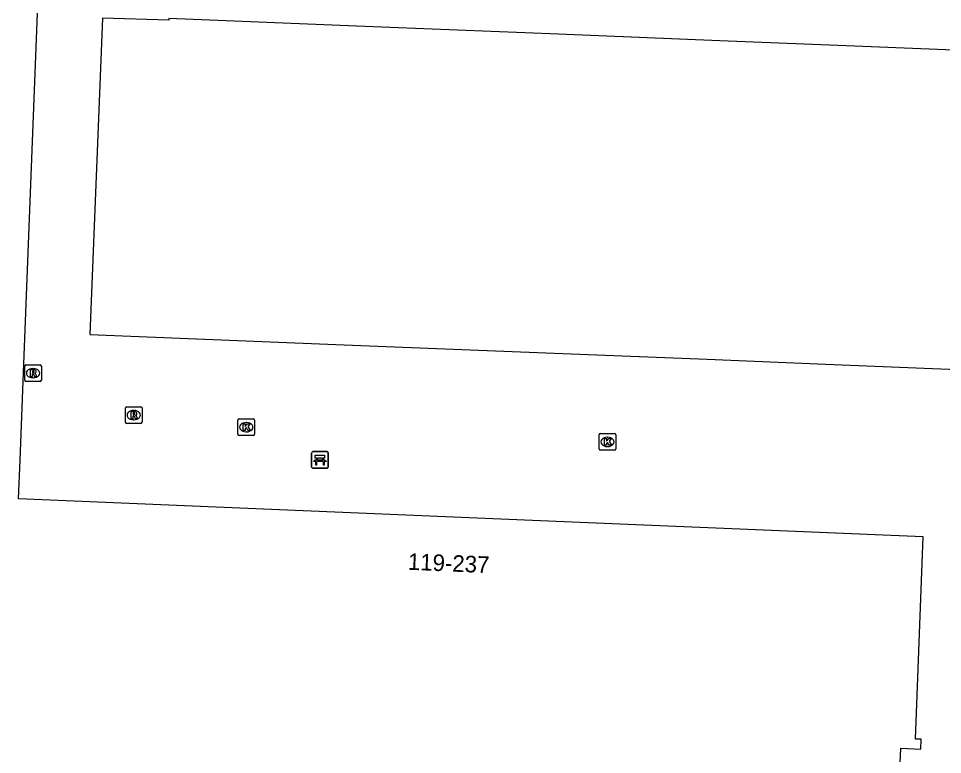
# Model space of a CAD drawing. Extents: x 160891 to 161384, y 386490 to 386907.
# Drawn here: x 161041.8 to 161097.4, y 386537.2 to 386581.5 of the extents above; entities that cross this region are included whole.
import ezdxf

# ---------------------------------------------------------------- set-up
doc = ezdxf.new("R2010")
doc.units = 0
for name, color, linetype in [('IMGEO_Bank', 7, 'Continuous'), ('IMGEO_Kolk', 7, 'Continuous'), ('IMGEO_Pand', 7, 'Continuous'), ('IMGEO_Pand_nummerreeks', 7, 'Continuous'), ('IMGEO_Rioolput', 7, 'Continuous')]:
    doc.layers.add(name, color=color, linetype=linetype)

msp = doc.modelspace()

# ---------------------------------------------------------------- linework, layer by layer
at = {"layer": 'IMGEO_Bank'}
for p, q in [((161059.471, 386554.487), (161059.471, 386555.328)), ((161059.471, 386555.328), (161059.471, 386554.487)), ((161059.546, 386555.412), (161060.387, 386555.412)), ((161060.387, 386555.412), (161059.546, 386555.412)), ((161060.471, 386555.337), (161060.471, 386554.496)), ((161060.471, 386554.496), (161060.471, 386555.337)), ((161060.168, 386554.81), (161059.775, 386554.81)), ((161059.78, 386554.918), (161059.78, 386555.024)), ((161059.824, 386555.024), (161059.824, 386554.918)), ((161060.112, 386555.03), (161059.83, 386555.03)), ((161059.83, 386554.912), (161060.112, 386554.912)), ((161060.118, 386554.918), (161060.118, 386555.024)), ((161060.162, 386555.024), (161060.162, 386554.918)), ((161060.396, 386554.412), (161059.555, 386554.412)), ((161059.555, 386554.412), (161060.396, 386554.412))]:
    msp.add_line(p, q, dxfattribs=at)
for points in [[(161059.774, 386555.03), (161059.688, 386555.03), (161059.688, 386555.191), (161060.251, 386555.191), (161060.251, 386555.03), (161060.168, 386555.03)], [(161059.718, 386554.81), (161059.576, 386554.81), (161059.688, 386554.912), (161059.774, 386554.912)], [(161059.768, 386554.803), (161059.768, 386554.596), (161059.725, 386554.596), (161059.725, 386554.803)], [(161060.168, 386554.912), (161060.251, 386554.912), (161060.363, 386554.81), (161060.224, 386554.81)], [(161060.218, 386554.803), (161060.218, 386554.596), (161060.174, 386554.596), (161060.174, 386554.803)]]:
    msp.add_lwpolyline(points, dxfattribs=at)
for centre, radius, start, end in [((161059.549, 386555.334), 0.0779, 92.4484, 184.2845), ((161059.549, 386555.334), 0.0779, 92.4484, 184.2845), ((161060.393, 386555.334), 0.0779, 2.4484, 94.2845), ((161060.393, 386555.334), 0.0779, 2.4484, 94.2845), ((161059.718, 386554.803), 0.00671, 2.8957, 87.1043), ((161059.775, 386554.803), 0.00671, 92.8957, 177.1043), ((161059.773, 386555.023), 0.00671, 2.8957, 87.1043), ((161059.773, 386554.919), 0.00671, 272.8957, 357.1043), ((161059.83, 386555.023), 0.00671, 92.8957, 177.1043), ((161059.83, 386554.919), 0.00671, 182.8957, 267.1043), ((161060.112, 386555.023), 0.00671, 2.8957, 87.1043), ((161060.112, 386554.919), 0.00671, 272.8957, 357.1043), ((161060.169, 386555.023), 0.00671, 92.8957, 177.1043), ((161060.169, 386554.919), 0.00671, 182.8957, 267.1043), ((161060.167, 386554.803), 0.00671, 2.8957, 87.1043), ((161060.224, 386554.803), 0.00671, 92.8957, 177.1043), ((161059.549, 386554.49), 0.0779, 182.4484, 274.2845), ((161059.549, 386554.49), 0.0779, 182.4484, 274.2845), ((161060.393, 386554.49), 0.0779, 272.4484, 4.2845), ((161060.393, 386554.49), 0.0779, 272.4484, 4.2845)]:
    msp.add_arc(centre, radius, start, end, dxfattribs=at)
at = {"layer": 'IMGEO_Kolk'}
for p, q in [((161055.035, 386556.459), (161055.035, 386557.311)), ((161055.11, 386557.385), (161055.962, 386557.385)), ((161055.523, 386557.165), (161055.548, 386557.165)), ((161056.036, 386557.311), (161056.036, 386556.459)), ((161055.962, 386556.385), (161055.11, 386556.385)), ((161055.546, 386556.605), (161055.521, 386556.605)), ((161076.769, 386555.574), (161076.769, 386556.426)), ((161076.844, 386556.5), (161077.696, 386556.5)), ((161077.77, 386556.426), (161077.77, 386555.574)), ((161077.257, 386556.28), (161077.282, 386556.28)), ((161077.696, 386555.5), (161076.844, 386555.5)), ((161077.28, 386555.72), (161077.255, 386555.72))]:
    msp.add_line(p, q, dxfattribs=at)
for points in [[(161055.035, 386556.459), (161055.035, 386557.311)], [(161055.11, 386557.385), (161055.962, 386557.385)], [(161055.356, 386557.085), (161055.479, 386557.085), (161055.479, 386556.934), (161055.609, 386557.085), (161055.773, 386557.085), (161055.627, 386556.934), (161055.78, 386556.685), (161055.628, 386556.685), (161055.543, 386556.849), (161055.479, 386556.782), (161055.479, 386556.685), (161055.356, 386556.685), (161055.356, 386557.085)], [(161056.036, 386557.311), (161056.036, 386556.459)], [(161055.962, 386556.385), (161055.11, 386556.385)], [(161076.769, 386555.574), (161076.769, 386556.426)], [(161076.844, 386556.5), (161077.696, 386556.5)], [(161077.77, 386556.426), (161077.77, 386555.574)], [(161077.09, 386556.2), (161077.213, 386556.2), (161077.213, 386556.049), (161077.343, 386556.2), (161077.507, 386556.2), (161077.361, 386556.049), (161077.514, 386555.8), (161077.362, 386555.8), (161077.277, 386555.964), (161077.213, 386555.897), (161077.213, 386555.8), (161077.09, 386555.8), (161077.09, 386556.2)], [(161077.696, 386555.5), (161076.844, 386555.5)]]:
    msp.add_lwpolyline(points, dxfattribs=at)
for centre, start, end in [((161055.112, 386557.309), 91.552, 178.448), ((161055.112, 386557.309), 91.552, 178.448), ((161055.96, 386557.309), 1.552, 88.448), ((161055.96, 386557.309), 1.552, 88.448), ((161055.112, 386556.461), 181.552, 268.448), ((161055.112, 386556.461), 181.552, 268.448), ((161055.96, 386556.461), 271.552, 358.448), ((161055.96, 386556.461), 271.552, 358.448), ((161076.846, 386556.424), 91.552, 178.448), ((161076.846, 386556.424), 91.552, 178.448), ((161077.694, 386556.424), 1.552, 88.448), ((161077.694, 386556.424), 1.552, 88.448), ((161076.846, 386555.576), 181.552, 268.448), ((161076.846, 386555.576), 181.552, 268.448), ((161077.694, 386555.576), 271.552, 358.448), ((161077.694, 386555.576), 271.552, 358.448)]:
    msp.add_arc(centre, 0.0765, start, end, dxfattribs=at)
for centre, major_axis, ratio, start_param, end_param in [((161055.522, 386556.885), (-0.387, 0.002), 0.722429, 4.712389, 7.853982), ((161055.547, 386556.885), (-0.39, 0.002), 0.717154, 1.570796, 4.712389), ((161077.256, 386556), (-0.387, 0.002), 0.722429, 4.712389, 7.853982), ((161077.281, 386556), (-0.39, 0.002), 0.717154, 1.570796, 4.712389)]:
    msp.add_ellipse(centre, major_axis=major_axis, ratio=ratio, start_param=start_param, end_param=end_param, dxfattribs=at)
at = {"layer": 'IMGEO_Pand'}
for points in [[(161113.546, 386663.894), (161112.853, 386646.718), (161112.621, 386640.934), (161112.559, 386639.396), (161112.378, 386634.915), (161112.255, 386631.87), (161111.098, 386603.328), (161110.606, 386591.176), (161110.319, 386584.108), (161110.116, 386579.09), (161091.136, 386579.854), (161084.022, 386580.14), (161074.316, 386580.531), (161062.171, 386581.019), (161050.874, 386581.474), (161050.87, 386581.374), (161046.888, 386581.503)], [(161051.083, 386511.057), (161051.206, 386511.052), (161052.017, 386528.899), (161080.022, 386527.764), (161080.132, 386529.382), (161081.504, 386529.308), (161086.537, 386529.035), (161086.775, 386534.825), (161095.779, 386534.461), (161095.797, 386534.862), (161094.798, 386534.906), (161094.918, 386537.567), (161096.112, 386537.502), (161096.134, 386538.109), (161095.807, 386538.111), (161096.256, 386550.282), (161074.659, 386551.192), (161041.832, 386552.576), (161041.925, 386554.908), (161042.136, 386560.18), (161042.986, 386581.802)], [(161046.888, 386581.503), (161046.117, 386562.468), (161061.417, 386561.851), (161073.561, 386561.361), (161083.268, 386560.969), (161090.381, 386560.682), (161128.539, 386559.143)]]:
    msp.add_lwpolyline(points, dxfattribs=at)
at = {"layer": 'IMGEO_Rioolput'}
for p, q in [((161042.207, 386559.71), (161042.207, 386560.562)), ((161042.282, 386560.636), (161043.134, 386560.636)), ((161042.695, 386560.416), (161042.72, 386560.416)), ((161043.208, 386560.562), (161043.208, 386559.71)), ((161043.134, 386559.636), (161042.282, 386559.636)), ((161042.718, 386559.856), (161042.693, 386559.856)), ((161048.264, 386557.188), (161048.264, 386558.04)), ((161048.339, 386558.114), (161049.191, 386558.114)), ((161049.265, 386558.04), (161049.265, 386557.188)), ((161048.752, 386557.894), (161048.777, 386557.894)), ((161049.191, 386557.114), (161048.339, 386557.114)), ((161048.775, 386557.334), (161048.75, 386557.334))]:
    msp.add_line(p, q, dxfattribs=at)
for points in [[(161042.207, 386559.71), (161042.207, 386560.562)], [(161042.282, 386560.636), (161043.134, 386560.636)], [(161042.796, 386560.334), (161042.544, 386560.336), (161042.544, 386559.936)], [(161042.722, 386560.255), (161042.668, 386560.255), (161042.668, 386560.174)], [(161043.208, 386560.562), (161043.208, 386559.71)], [(161043.134, 386559.636), (161042.282, 386559.636)], [(161042.544, 386559.936), (161042.668, 386559.936), (161042.668, 386560.098), (161042.679, 386560.098)], [(161042.668, 386560.174), (161042.72, 386560.174)], [(161042.726, 386560.069), (161042.797, 386559.936), (161042.937, 386559.936), (161042.872, 386560.062)], [(161048.264, 386557.188), (161048.264, 386558.04)], [(161048.339, 386558.114), (161049.191, 386558.114)], [(161049.265, 386558.04), (161049.265, 386557.188)], [(161048.853, 386557.812), (161048.601, 386557.814), (161048.601, 386557.414)], [(161048.601, 386557.414), (161048.725, 386557.414), (161048.725, 386557.576), (161048.736, 386557.576)], [(161048.779, 386557.733), (161048.725, 386557.733), (161048.725, 386557.652)], [(161048.725, 386557.652), (161048.777, 386557.652)], [(161048.783, 386557.547), (161048.854, 386557.414), (161048.994, 386557.414), (161048.929, 386557.54)], [(161049.191, 386557.114), (161048.339, 386557.114)]]:
    msp.add_lwpolyline(points, dxfattribs=at)
for centre, radius, start, end in [((161042.284, 386560.56), 0.0765, 91.552, 178.448), ((161042.284, 386560.56), 0.0765, 91.552, 178.448), ((161042.728, 386560.159), 0.0964, 77.0061, 93.1865), ((161042.742, 386560.216), 0.0378, 276.6634, 79.6772), ((161042.795, 386560.224), 0.109, 350.3612, 89.416), ((161042.793, 386560.224), 0.112, 277.5842, 350.9817), ((161043.132, 386560.56), 0.0765, 1.552, 88.448), ((161043.132, 386560.56), 0.0765, 1.552, 88.448), ((161042.284, 386559.712), 0.0765, 181.552, 268.448), ((161042.284, 386559.712), 0.0765, 181.552, 268.448), ((161042.678, 386560.045), 0.0533, 26.0293, 88.6989), ((161042.704, 386560.363), 0.19, 274.7715, 282.9687), ((161042.777, 386560.009), 0.108, 29.5134, 73.7905), ((161043.132, 386559.712), 0.0765, 271.552, 358.448), ((161043.132, 386559.712), 0.0765, 271.552, 358.448), ((161048.341, 386558.038), 0.0765, 91.552, 178.448), ((161048.341, 386558.038), 0.0765, 91.552, 178.448), ((161049.189, 386558.038), 0.0765, 1.552, 88.448), ((161049.189, 386558.038), 0.0765, 1.552, 88.448), ((161048.735, 386557.523), 0.0533, 26.0293, 88.6989), ((161048.761, 386557.841), 0.19, 274.7715, 282.9687), ((161048.785, 386557.637), 0.0964, 77.0061, 93.1865), ((161048.799, 386557.694), 0.0378, 276.6634, 79.6772), ((161048.852, 386557.702), 0.109, 350.3612, 89.416), ((161048.85, 386557.702), 0.112, 277.5842, 350.9817), ((161048.834, 386557.487), 0.108, 29.5134, 73.7905), ((161048.341, 386557.19), 0.0765, 181.552, 268.448), ((161048.341, 386557.19), 0.0765, 181.552, 268.448), ((161049.189, 386557.19), 0.0765, 271.552, 358.448), ((161049.189, 386557.19), 0.0765, 271.552, 358.448)]:
    msp.add_arc(centre, radius, start, end, dxfattribs=at)
for centre, major_axis, ratio, start_param, end_param in [((161042.694, 386560.136), (-0.387, 0.002), 0.722429, 4.712389, 7.853982), ((161042.719, 386560.136), (-0.39, 0.002), 0.717154, 1.570796, 4.712389), ((161048.751, 386557.614), (-0.387, 0.002), 0.722429, 4.712389, 7.853982), ((161048.776, 386557.614), (-0.39, 0.002), 0.717154, 1.570796, 4.712389)]:
    msp.add_ellipse(centre, major_axis=major_axis, ratio=ratio, start_param=start_param, end_param=end_param, dxfattribs=at)

# ---------------------------------------------------------------- texts
at = {"layer": 'IMGEO_Pand_nummerreeks'}
msp.add_text('119-237', height=1, rotation=357.5864, dxfattribs=at).set_placement((161065.242, 386548.306))

doc.saveas('drawing.dxf')
